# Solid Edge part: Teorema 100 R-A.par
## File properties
Title: TEOREMA 100/R A
Author: DESYS
Template: Iso Part.par
Last saved by: i.fialdini
Revision: 55
Application: Solid Edge
Tipo di contenuto documento: 0
Accuracy: 0.990
Document Number: 8031R100/A
Revision: 0
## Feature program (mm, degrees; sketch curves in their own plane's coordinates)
sketch for "unnamed Protrusion 1" plane through (10.8674, 10.8674, 0) normal (0, 0, 1) x-axis (1, 0, 0)
  line (-510.8674, 219.1326) -> (489.1326, 219.1326)
  line (489.1326, 219.1326) -> (489.1326, -240.8674)
  line (489.1326, -240.8674) -> (-510.8674, -240.8674)
  line (-510.8674, -240.8674) -> (-510.8674, 219.1326)
  dimension (linear) = 510.8674
  dimension (linear) = 510.8674
  dimension (linear) = 489.1326
  dimension (linear) = 489.1326
extrude "unnamed Protrusion 1" add finite 140 along -normal
sketch for "ScavoEstrusione_1" plane through (0, 0, 0) normal (0, 0, 1) x-axis (1, 0, 0)
  line (0, 0) -> (0, 0)
  line (0, 0) -> (0, 0)
  line (-485, -100) -> (485, -100)
  line (485, -100) -> (485, 215)
  line (-485, 215) -> (485, 215)
  line (-485, 215) -> (-485, -100)
  dimension (linear) = 485
  dimension (linear) = 485
extrude "ScavoEstrusione_1" cut finite 80 along -normal
sketch for "ScavoEstrusione_7" plane through (0, 0, -140) normal (0, 0, -1) x-axis (1, 0, 0)
  line (-400, 110) -> (400, 110)
  line (400, 205) -> (400, 110)
  line (-400, 205) -> (400, 205)
  line (-400, 110) -> (-400, 205)
  dimension (linear) = 400
  dimension (linear) = 400
  dimension (linear) = 400
  dimension (linear) = 400
extrude "ScavoEstrusione_7" cut finite 120 along -normal
sketch for "ScavoEstrusione_8" plane through (0, 0, -140) normal (0, 0, -1) x-axis (1, 0, 0)
  line (-440, -170) -> (440, -170)
  line (-440, 10.1259) -> (-440, -170)
  line (-400, 60.0629) -> (-440, 10.1259)
  line (-400, 110) -> (-400, 60.0629)
  line (-400, 110) -> (400, 110)
  line (400, 110) -> (400, 60.0629)
  line (400, 60.0629) -> (440, 10.1259)
  line (440, 10.1259) -> (440, -170)
  dimension (linear) = 440
  dimension (linear) = 440
  dimension (linear) = 400
  dimension (linear) = 400
  dimension (linear) = 400
extrude "ScavoEstrusione_8" cut finite 40 along -normal
sketch for "v_3" #1 plane through (0, 0, -140) normal (0, 0, -1) x-axis (1, 0, 0)
  line (-440, 9.8811) -> (-440, 205)
  line (-400, 205) -> (-440, 205)
  line (-400, 60.0629) -> (-400, 205)
  line (-400, 60.0629) -> (-440, 9.8811)
  dimension (linear) = 440
  dimension (linear) = 400
  dimension (linear) = 400
  dimension (linear) = 400
sketch for "v_3" #2 plane through (0, 0, -140) normal (0, 0, -1) x-axis (1, 0, 0)
  line (440, 9.8811) -> (440, 205)
  line (400, 205) -> (440, 205)
  line (400, 60.0629) -> (400, 205)
  line (400, 60.0629) -> (440, 9.8811)
extrude "v_3" cut finite 5 along -normal
sketch for "ScavoEstrusione_10" plane through (0, 0, 0) normal (0, 0, 1) x-axis (0, -1, 0)
  line (100, -485) -> (215, -485)
  line (215, -485) -> (215, 485)
  line (215, 485) -> (100, 485)
  line (100, 485) -> (100, -485)
extrude "ScavoEstrusione_10" cut finite 10 along -normal
sketch for "ScavoEstrusione_11" plane through (0, -157.5, -10) normal (0, 0, 1) x-axis (-1, 0, 0)
  circle centre (0, 0) radius 20
extrude "ScavoEstrusione_11" cut finite 665 along -normal
sketch for "unnamed Cutout 1" plane through (0, -100, -45) normal (0, 1, 0) x-axis (-1, 0, 0)
  circle centre (0, 2.5) radius 12.5
extrude "unnamed Cutout 1" cut to key point along -normal
sketch for "ScavoEstrusione_14" #1 plane through (0, -230, -70) normal (0, -1, 0) x-axis (1, 0, 0)
  line (-309.7178, -22.5019) -> (-300.1617, -22.5019)
  arc centre (-300.1617, -9.7819) radius 12.72 from (-287.4436, -10.0019) to (-300.1617, -22.5019) cw
  arc centre (-300.1617, -10.2219) radius 12.72 from (-287.4436, -10.0019) to (-300.1617, 2.4981) ccw
  line (-309.7217, 2.4981) -> (-300.1617, 2.4981)
  arc centre (-309.7217, -10.2219) radius 12.72 from (-322.4398, -10) to (-309.7217, 2.4981) cw
  arc centre (-309.7178, -9.778) radius 12.7239 from (-309.7178, -22.5019) to (-322.4398, -10) cw
sketch for "ScavoEstrusione_14" #2 plane through (0, -230, -70) normal (0, -1, 0) x-axis (1, 0, 0)
  line (309.7178, -22.5019) -> (300.1617, -22.5019)
  arc centre (300.1617, -9.7819) radius 12.72 from (287.4436, -10.0019) to (300.1617, -22.5019) ccw
  arc centre (300.1617, -10.2219) radius 12.72 from (287.4436, -10.0019) to (300.1617, 2.4981) cw
  line (309.7217, 2.4981) -> (300.1617, 2.4981)
  arc centre (309.7217, -10.2219) radius 12.72 from (322.4398, -10) to (309.7217, 2.4981) ccw
  arc centre (309.7178, -9.778) radius 12.7239 from (309.7178, -22.5019) to (322.4398, -10) ccw
extrude "ScavoEstrusione_14" cut finite 35 along -normal
sketch for "ProtrusioneEstrusa_2" plane through (0, 30, -100) normal (0, 0, -1) x-axis (-1, 0, 0)
  circle centre (0, -15) radius 35
extrude "ProtrusioneEstrusa_2" add finite 30 along +normal
sketch for "ScavoEstrusione_15" plane through (-0.8459, 15.0679, -130) normal (0, 0, -1) x-axis (-1, 0, 0)
  circle centre (-0.8459, -0.0679) radius 30
extrude "ScavoEstrusione_15" cut finite 455 along -normal
sketch for "ScavoEstrusione_16" #1 plane through (-400, -132.5315, -77.5) normal (1, 0, 0) x-axis (0, -1, 0)
  circle centre (40.3976, 16.9065) radius 7.5
sketch for "ScavoEstrusione_16" #2 plane through (-400, -132.5315, -77.5) normal (1, 0, 0) x-axis (0, -1, 0)
  circle centre (-753.2679, -1216.4618) radius 7.5
sketch for "ScavoEstrusione_16" #3 plane through (-400, -132.5315, -77.5) normal (1, 0, 0) x-axis (0, -1, 0)
  circle centre (40.3976, 16.9065) radius 7.5
extrude "ScavoEstrusione_16" cut finite 35 along -normal
draft "Spoglia_1"  Angles1 = 5 deg
draft "Spoglia_2"  Angles1 = 5 deg
draft "Spoglia_4"  Angles1 = 4 deg
draft "Spoglia_5"  Angles1 = 4 deg
draft "Spoglia_6"  Angles1 = 4 deg
draft "Spoglia_7"  Angles1 = 5 deg
draft "Spoglia_8"  Angles1 = 5 deg
sketch for "ProtrusioneEstrusa_4" plane through (0, 0, -70) normal (1, 0, 0) x-axis (0, -1, 0)
  line (20, 55) -> (130, 55)
  line (130, 55) -> (130, -50)
  line (130, -50) -> (110, -50)
  line (110, -50) -> (110, 30)
  line (51.3251, 30) -> (110, 30)
extrude "ProtrusioneEstrusa_4" add finite 50 symmetric
sketch for "unnamed Protrusion 2" plane through (-0.8459, -130, -72.5) normal (0, -1, 0) x-axis (-1, 0, 0)
  line (-25.8459, -7.5) -> (-85.8459, -52.5)
extrude "unnamed Protrusion 2" add through along -normal
fillet "Rotondo_4" radius 35
fillet "Rotondo_5" radius 40
fillet "Rotondo_6" radius 7
fillet "Rotondo_8" radius 5
fillet "Rotondo_10" radius 5
fillet "Rotondo_12" radius 5
fillet "Rotondo_13" radius 5
fillet "Rotondo_14" radius 5
fillet "Rotondo_15" radius 10
fillet "Rotondo_16" radius 3
fillet "Rotondo_17" radius 7.5
fillet "Rotondo_18" radius 7.5
fillet "Rotondo_19" radius 7.5
fillet "Rotondo_20" radius 7.5
sketch for "unnamed Cutout 2" plane through (0, 0, -70) normal (1, 0, 0) x-axis (0, -1, 0)
extrude "unnamed Cutout 2" cut finite 40 symmetric
fillet "Rotondo_21" radius 2
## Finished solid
Body 1: solid body, 213 faces, 468 edges, 257 vertices.
  Faces by surface: cylinder 100, torus 39, plane 38, blend 31, sphere 5
  Edges by curve: circle 198, line 186, ellipse 49, intersection 35
Bounding box of the edges (mm; curved faces can reach further): 1000.000 x 460.000 x 140.000, from (-500, -230, -140) to (500, 230, 0).
Cylindrical faces by radius (mm): R2 x8, R5 x38, R7 x4, R7.5 x25, R10 x4, R12.5 x1, R12.72 x6, R12.7239 x2, R20 x1, R30 x1, R35 x6, R40 x4
Toroidal faces (ring radius, tube radius in mm): R2.5 r7.5 x8, R10 r5 x6, R12 r5 x1, R14.72 r2 x12, R14.7239 r2 x4, R15.5 r3 x1, R23 r3 x1, R28 r7 x2, R40 r10 x1, R42.5 r7.5 x1, R47.5 r7.5 x2
Spherical faces by radius (mm): R5 x5
Planar faces by outward normal: +x 4, +y 4, +z 5, -x 3, -y 5, -z 9, oblique 8
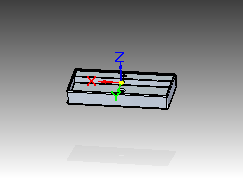
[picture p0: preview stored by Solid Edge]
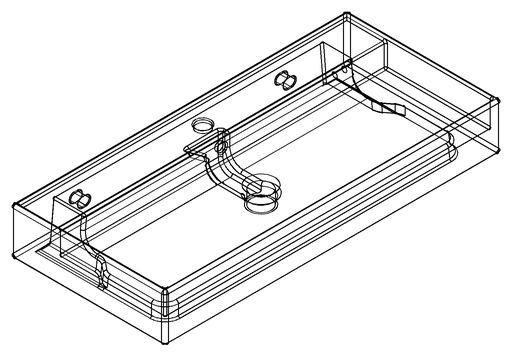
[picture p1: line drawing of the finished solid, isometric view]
